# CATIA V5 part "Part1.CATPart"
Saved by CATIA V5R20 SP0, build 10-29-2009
Part number: Part1
Bounding box of the stored display mesh (mm): x -20 to 25, y -55 to 55, z 0 to 149.99
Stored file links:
  E:\Ehsan\Amoozesh\CATIA\CATIA Course\Advanced\Exercises\DMU Kinematic\1\Part1.CATPart
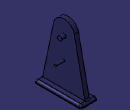
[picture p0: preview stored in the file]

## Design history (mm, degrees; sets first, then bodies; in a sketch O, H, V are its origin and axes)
Body1 (main body)
  Sketch1 on yz-plane, origin (0, 0, 0), H (0, 1, 0), V (0, 0, 1)
    point P1 (-55, 0)
    line L1 (-55, 0) -> (55, 0)
    line L2 (55, 0) -> (55, 2)
    line L3 (50, 7) -> (-50, 7)
    line L4 (-55, 2) -> (-55, 0)
    circle A1 centre (0, 65) radius 2.5
    point P3 (0, 65)
    circle A2 centre (0, 115) radius 5
    point P4 (0, 115)
    arc A3 centre (0, 125) radius 25 from (24.4793, 130.076) to (-24.4793, 130.076) ccw
    point P5 (0, 125)
    arc A4 centre (50, 2) radius 5 from (55, 2) to (50, 7) ccw
    arc A5 centre (-50, 2) radius 5 from (-50, 7) to (-55, 2) ccw
    point P9 (-50, 7)
    line L5 (-50, 7) -> (-24.4793, 130.076)
    point P12 (-50, 7)
    point P13 (-24.4793, 130.076)
    point P14 (24.4793, 130.076)
    point P15 (50, 7)
    line L6 (50, 7) -> (24.4793, 130.076)
    distance P1 V = 55
    distance P1 H = 0
    distance L1 L3 = 7
    distance L2 L4 = 110
    distance P3 V = 0
    distance P3 H = 65
    radius A1 = 2.5
    distance P4 V = 0
    distance P4 H = 115
    radius A2 = 5
    distance P5 H = 125
    radius A3 = 25
    radius A4 = 5
    radius A5 = 5 {= Sketch1.radius(A4)}
    horizontal: L1 H, L3 H
    vertical: L2 V, L4 V
    tangency: A4 L2, A4 L3, A5 L3, A5 L4, L5 A3
    coincidence: P9 P12
    symmetry: P13 P14 V, P12 P15 V, L5 L6 V
  MultiPad1: profile Sketch1, domains (length 20 / length 20; length 5 / length 5; length 15 / length 5; length 25 / length 5)
  Fillet1: radius 5, on edge [face of MultiPad1 from Sketch1.L3 | face of MultiPad1]; edge [face of MultiPad1 | face of MultiPad1 from Sketch1.L3]
  Fillet2: radius 5, on edge [face of MultiPad1 from Sketch1.L6 | face of MultiPad1 from Sketch1.A4]; edge [face of MultiPad1 from Sketch1.A5 | face of MultiPad1 from Sketch1.L5]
